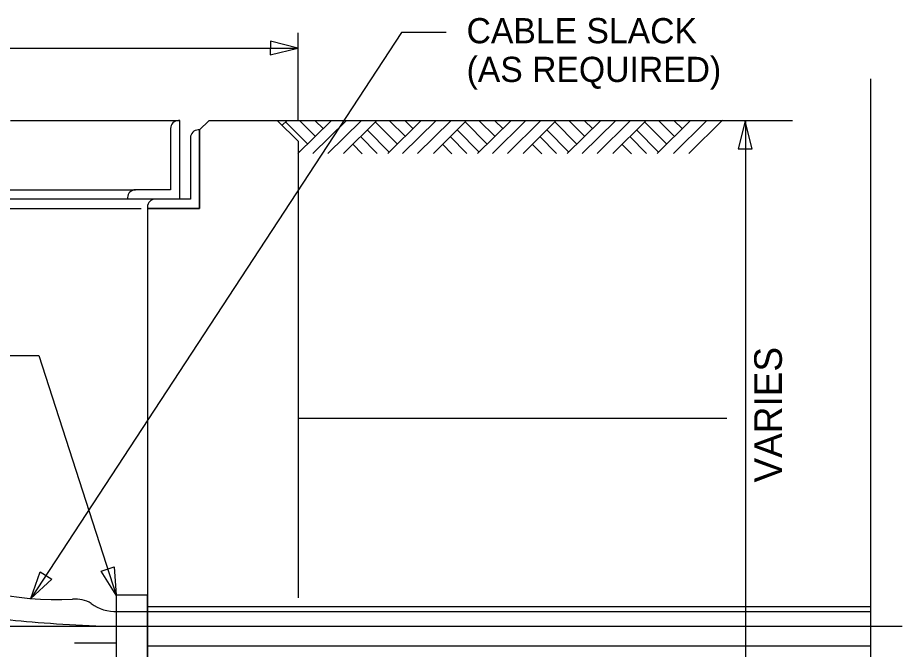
# Model space of a CAD drawing. Extents: x 1299104.8 to 1299141.6, y 239639.8 to 239661.8.
# Drawn here: x 1299116.233 to 1299120.075, y 239648.528 to 239651.27 of the extents above; entities that cross this region are included whole.
import ezdxf

# ---------------------------------------------------------------- set-up
doc = ezdxf.new("R2010")
doc.units = 0
doc.layers.add('DIM TXT', color=7, linetype='Continuous')

msp = doc.modelspace()

# ---------------------------------------------------------------- linework, layer by layer
at = {"layer": 'DIM TXT'}
for p, q in [((1299117.4513, 239650.8231), (1299117.4513, 239651.2043)), ((1299113.2794, 239651.1374), (1299117.4513, 239651.1374)), ((1299119.9371, 239651.0055), (1299119.9371, 239648.2261)), ((1299116.2016, 239650.8237), (1299116.9375, 239650.8237)), ((1299116.9375, 239650.8237), (1299116.9314, 239650.8237)), ((1299116.9314, 239650.8237), (1299116.9314, 239650.8237)), ((1299117.362, 239650.8231), (1299117.0635, 239650.8231)), ((1299117.451, 239650.7341), (1299117.362, 239650.8231)), ((1299119.5977, 239650.8231), (1299117.362, 239650.8231)), ((1299117.3816, 239650.8034), (1299117.4015, 239650.8231)), ((1299117.4503, 239650.68), (1299117.5945, 239650.8231)), ((1299117.4581, 239650.8231), (1299117.5254, 239650.7553)), ((1299117.5152, 239650.68), (1299117.6594, 239650.8231)), ((1299117.5254, 239650.8231), (1299117.5597, 239650.7886)), ((1299117.5801, 239650.68), (1299117.7243, 239650.8231)), ((1299117.6485, 239650.6813), (1299117.7913, 239650.8231)), ((1299117.8402, 239650.68), (1299117.9844, 239650.8231)), ((1299117.8479, 239650.8231), (1299117.9152, 239650.7553)), ((1299117.905, 239650.68), (1299118.0493, 239650.8231)), ((1299117.9153, 239650.8231), (1299117.9496, 239650.7886)), ((1299117.9699, 239650.68), (1299118.1141, 239650.8231)), ((1299118.0383, 239650.6813), (1299118.1812, 239650.8231)), ((1299118.23, 239650.68), (1299118.3742, 239650.8231)), ((1299118.2378, 239650.8231), (1299118.3051, 239650.7553)), ((1299118.2949, 239650.68), (1299118.4391, 239650.8231)), ((1299118.3051, 239650.8231), (1299118.3394, 239650.7886)), ((1299118.3598, 239650.68), (1299118.504, 239650.8231)), ((1299118.4282, 239650.6813), (1299118.571, 239650.8231)), ((1299118.6199, 239650.68), (1299118.7641, 239650.8231)), ((1299118.6276, 239650.8231), (1299118.6949, 239650.7553)), ((1299118.6847, 239650.68), (1299118.8289, 239650.8231)), ((1299118.695, 239650.8231), (1299118.7293, 239650.7886)), ((1299118.7496, 239650.68), (1299118.8938, 239650.8231)), ((1299118.818, 239650.6813), (1299118.9609, 239650.8231)), ((1299119.0102, 239650.6805), (1299119.1539, 239650.8231)), ((1299119.0175, 239650.8231), (1299119.0848, 239650.7553)), ((1299119.0808, 239650.6802), (1299119.2248, 239650.8231)), ((1299119.0848, 239650.8231), (1299119.1191, 239650.7886)), ((1299119.1477, 239650.68), (1299119.2936, 239650.8249)), ((1299119.3934, 239650.8231), (1299119.3934, 239647.5241)), ((1299117.3965, 239650.8181), (1299117.4926, 239650.7213)), ((1299117.7863, 239650.8181), (1299117.8825, 239650.7213)), ((1299118.1762, 239650.8181), (1299118.2723, 239650.7213)), ((1299118.566, 239650.8181), (1299118.6622, 239650.7213)), ((1299118.9559, 239650.8181), (1299119.052, 239650.7213)), ((1299117.0234, 239650.783), (1299117.0173, 239650.783)), ((1299117.0234, 239650.783), (1299117.0234, 239650.4425)), ((1299117.7214, 239650.7538), (1299117.794, 239650.6807)), ((1299117.7513, 239650.7834), (1299117.8467, 239650.6872)), ((1299118.1113, 239650.7538), (1299118.1838, 239650.6807)), ((1299118.1411, 239650.7834), (1299118.2366, 239650.6872)), ((1299118.5011, 239650.7538), (1299118.5737, 239650.6807)), ((1299118.531, 239650.7834), (1299118.6264, 239650.6872)), ((1299118.891, 239650.7538), (1299118.9635, 239650.6807)), ((1299118.9208, 239650.7834), (1299119.0163, 239650.6872)), ((1299117.4513, 239650.7337), (1299117.4513, 239648.7515)), ((1299117.4513, 239650.7337), (1299117.4513, 239648.7515)), ((1299117.688, 239650.7205), (1299117.7293, 239650.6787)), ((1299118.0778, 239650.7205), (1299118.1192, 239650.6787)), ((1299118.4677, 239650.7205), (1299118.509, 239650.6787)), ((1299118.8575, 239650.7205), (1299118.8989, 239650.6787)), ((1299117.4513, 239650.6929), (1299117.4569, 239650.6872)), ((1299113.9801, 239650.5233), (1299116.7445, 239650.5233)), ((1299114.0141, 239650.4832), (1299116.7105, 239650.4832)), ((1299116.7105, 239650.4892), (1299116.7105, 239650.4832)), ((1299114.2462, 239650.4425), (1299116.4116, 239650.4425)), ((1299116.4116, 239650.4425), (1299116.7695, 239650.4425)), ((1299116.7964, 239650.4485), (1299116.7964, 239650.4425)), ((1299117.0234, 239650.4425), (1299116.7964, 239650.4425)), ((1299116.7964, 239650.4425), (1299116.7964, 239649.8258)), ((1299116.7964, 239649.8258), (1299116.7964, 239648.1261)), ((1299117.451, 239649.8102), (1299117.451, 239648.7603)), ((1299117.4513, 239649.5317), (1299119.313, 239649.5317)), ((1299117.8828, 239648.7118), (1299116.7964, 239648.7118)), ((1299119.9371, 239648.712), (1299117.451, 239648.712)), ((1299116.6659, 239648.6925), (1299119.9371, 239648.6925)), ((1299120.075, 239648.6265), (1299110.9016, 239648.6265)), ((1299116.6602, 239648.5552), (1299116.4794, 239648.5552)), ((1299117.883, 239648.5412), (1299116.7964, 239648.5412)), ((1299119.9371, 239648.5414), (1299117.451, 239648.5414))]:
    msp.add_line(p, q, dxfattribs=at)
for points in [[(1299118.0938, 239651.2061), (1299117.9005, 239651.2061), (1299116.2905, 239648.7485)], [(1299116.7105, 239650.4832), (1299116.9375, 239650.4832), (1299116.9375, 239650.8237)], [(1299117.2423, 239650.8231), (1299117.0635, 239650.8231), (1299117.0234, 239650.783)], [(1299116.8974, 239650.7896), (1299116.8974, 239650.5233), (1299116.7445, 239650.5233)], [(1299116.7964, 239650.4425), (1299117.0234, 239650.4425), (1299117.0234, 239650.783)], [(1299116.9833, 239650.7489), (1299116.9833, 239650.4826), (1299116.8304, 239650.4826)], [(1299116.0543, 239649.803), (1299116.325, 239649.803), (1299116.6602, 239648.7627)]]:
    msp.add_lwpolyline(points, dxfattribs=at)
for points in [[(1299117.3302, 239651.1084), (1299117.4504, 239651.1378), (1299117.3306, 239651.1684)], [(1299119.4225, 239650.7007), (1299119.3931, 239650.8209), (1299119.3625, 239650.701)], [(1299116.3811, 239648.8322), (1299116.2905, 239648.748), (1299116.3309, 239648.8649)], [(1299116.6526, 239648.8858), (1299116.6607, 239648.7624), (1299116.5954, 239648.8674)], [(1299116.7964, 239648.4903), (1299116.7964, 239648.7627), (1299116.6602, 239648.7627), (1299116.6602, 239648.4903)]]:
    msp.add_lwpolyline(points, close=True, dxfattribs=at)
for centre, radius, start, end in [((1299116.9314, 239650.7896), 0.034, 90, 180), ((1299117.0173, 239650.7489), 0.034, 90, 180), ((1299116.7445, 239650.4892), 0.034, 90, 180), ((1299116.8304, 239650.4486), 0.034, 90, 180), ((1299116.4044, 239650.1451), 1.4012, 242.4172, 272.7502), ((1299116.4836, 239648.6089), 0.1371, 59.7242, 95.0241), ((1299116.6554, 239648.8595), 0.1673, 232.1664, 273.5994)]:
    msp.add_arc(centre, radius, start, end, dxfattribs=at)
msp.add_open_spline([(1299114.0645, 239648.6265), (1299114.8919, 239648.6735), (1299114.9208, 239648.9681), (1299115.0306, 239649.1125), (1299115.3626, 239649.1723), (1299115.5799, 239649.153), (1299115.7302, 239649.0317), (1299115.7524, 239648.7447), (1299115.7186, 239648.5926), (1299115.47, 239648.5464), (1299115.1116, 239648.5348), (1299114.9381, 239648.685), (1299114.8861, 239648.9912), (1299115.048, 239649.1934), (1299115.4122, 239649.257), (1299115.6875, 239649.1745), (1299115.8342, 239649.0432), (1299115.8062, 239648.644), (1299116.6602, 239648.6265)], degree=2, dxfattribs=at)

# ---------------------------------------------------------------- texts
for s, p in [('CABLE SLACK', (1299118.1827, 239651.1593)), ('(AS REQUIRED)', (1299118.1827, 239650.9912))]:
    msp.add_text(s, height=0.109433, dxfattribs=at).set_placement(p)
msp.add_text('VARIES', height=0.12, rotation=90, dxfattribs=at).set_placement((1299119.552, 239649.2521))

doc.saveas('drawing.dxf')
